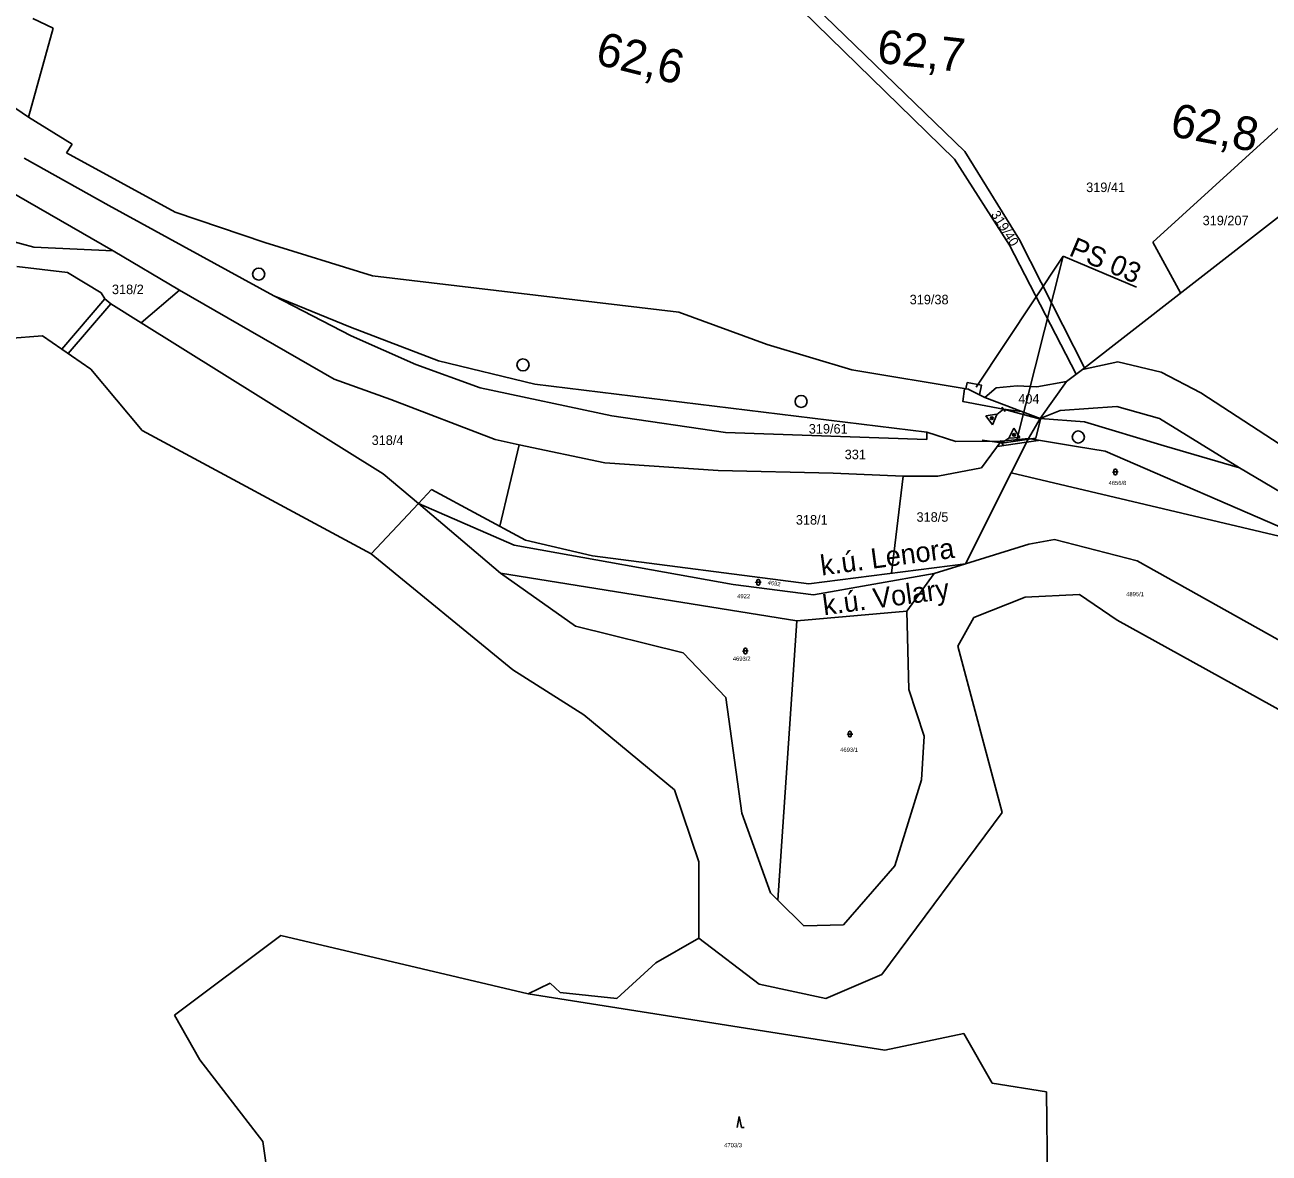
# Model space of a CAD drawing. Extents: x -805826 to -803822, y -1165880 to -1164382.
# Drawn here: x -805114.2 to -804669.5, y -1165376.6 to -1164973.4 of the extents above; entities that cross this region are included whole.
import ezdxf

# ---------------------------------------------------------------- set-up
doc = ezdxf.new("R2010")
doc.units = 0
for name, color, linetype in [('Default', 7, 'Continuous'), ('kilometráž - 2880', 7, 'Continuous'), ('kn_celek - Cisla pozemkovych parcel', 7, 'Continuous'), ('kn_celek - Hranice KU 1_2880', 7, 'Continuous'), ('kn_celek - Hranice parcel', 7, 'Continuous'), ('kn_celek - názvy ku 1_2880', 7, 'Continuous'), ('kn_celek - Vnitrni kresby', 7, 'Continuous'), ('kn_celek - Znacky kultur', 7, 'Continuous'), ('plochy - DZ_ostat', 7, 'Continuous'), ('plochy - SZDC', 7, 'Continuous'), ('plochy - TZ_zpf', 7, 'Continuous'), ('PSR_C2_3_celsit_Lenora - PS03', 7, 'Continuous'), ('SOPS', 7, 'Continuous')]:
    doc.layers.add(name, color=color, linetype=linetype)

# ---------------------------------------------------------------- blocks, each defined once
blk = doc.blocks.new('316')
at = {"layer": 'Default'}
for p, q in [((-8.3, 10), (-10, 8.1)), ((-5, 10), (-8.3, 10)), ((-5, 15.5), (-5, 4.5)), ((-5, 10), (5, 10)), ((0.5, 20), (-0.5, 20)), ((-0.5, 0), (0.5, 0)), ((5, 4.5), (5, 15.5)), ((10, 10), (5, 10))]:
    blk.add_line(p, q, dxfattribs=at)
for centre, start, end in [((-0.5, 15.5), 90, 180), ((-0.5, 4.5), 180, 270), ((0.5, 15.5), 0, 90), ((0.5, 4.5), 270, 0)]:
    blk.add_arc(centre, 4.5, start, end, dxfattribs=at)
blk = doc.blocks.new('308')
at = {"layer": 'Default'}
for p, q in [((-7.5, 0.2), (0, 40.2)), ((0, 40.2), (7.5, 0.2)), ((7.5, 0.2), (17.5, 0.2))]:
    blk.add_line(p, q, dxfattribs=at)

msp = doc.modelspace()

# ---------------------------------------------------------------- linework, layer by layer
at = {"layer": 'kilometráž - 2880'}
for centre in [(-805030.64, -1165062.45), (-804936.17, -1165094.91), (-804836.78, -1165107.96), (-804737.69, -1165120.69)]:
    msp.add_circle(centre, 2.16, dxfattribs=at)
at = {"layer": 'kn_celek - Hranice KU 1_2880'}
for p, q in [((-804701.79, -1165069.72), (-804618.36, -1165004.7)), ((-804736.13, -1165096.49), (-804701.79, -1165069.72)), ((-805120.21, -1165085.52), (-805107.91, -1165084.54)), ((-805107.91, -1165084.54), (-805090.67, -1165096.41)), ((-805090.67, -1165096.41), (-805072.24, -1165118.38)), ((-804741.92, -1165100.8), (-804736.13, -1165096.49)), ((-804751.26, -1165114.04), (-804741.92, -1165100.8)), ((-805072.24, -1165118.38), (-804990.43, -1165162.44)), ((-804761.65, -1165133.49), (-804755.48, -1165121.19)), ((-804777.95, -1165165.95), (-804761.65, -1165133.49)), ((-804973.55, -1165144.43), (-804968.85, -1165139.42)), ((-804968.85, -1165139.42), (-804935.25, -1165157.52)), ((-804990.43, -1165162.44), (-804973.55, -1165144.43)), ((-804935.25, -1165157.52), (-804911.29, -1165163.1)), ((-804911.29, -1165163.1), (-804834.02, -1165173.21)), ((-804834.02, -1165173.21), (-804777.95, -1165165.95))]:
    msp.add_line(p, q, dxfattribs=at)
at = {"layer": 'kn_celek - Hranice parcel'}
for p, q in [((-804837.56, -1164961.21), (-804778.25, -1165018.66)), ((-804781.99, -1165021.41), (-804842.42, -1164962.28)), ((-805112.96, -1165006.31), (-805104.08, -1164974.52)), ((-805104.08, -1164974.52), (-805111.37, -1164971.04)), ((-804711.07, -1165051.06), (-804629.65, -1164976.8)), ((-805139.43, -1164988.32), (-805112.96, -1165006.31)), ((-805174.61, -1165001.14), (-805082.67, -1165054.14)), ((-804701.79, -1165069.72), (-804618.36, -1165004.7)), ((-805097.29, -1165016.07), (-805112.96, -1165006.31)), ((-805099.28, -1165019.07), (-805097.29, -1165016.07)), ((-805060.5, -1165040.27), (-805099.28, -1165019.07)), ((-804778.25, -1165018.66), (-804758.75, -1165050.15)), ((-805084.18, -1165037.92), (-805114.48, -1165020.99)), ((-804762.33, -1165052.09), (-804781.99, -1165021.41)), ((-805111.01, -1165052.83), (-805172.69, -1165036.29)), ((-805025.27, -1165070.2), (-805084.18, -1165037.92)), ((-805028.48, -1165051.18), (-805060.5, -1165040.27)), ((-804758.75, -1165050.15), (-804735.46, -1165095.96)), ((-805111.01, -1165052.83), (-805082.67, -1165054.14)), ((-805082.67, -1165054.14), (-805058.92, -1165068.18)), ((-804989.96, -1165063.05), (-805028.48, -1165051.18)), ((-804762.33, -1165052.09), (-804738.45, -1165098.21)), ((-804701.13, -1165069.2), (-804711.07, -1165051.06)), ((-805098.97, -1165061.86), (-805117.06, -1165059.74)), ((-805086.95, -1165069.13), (-805098.97, -1165061.86)), ((-804880.41, -1165076.04), (-804989.96, -1165063.05)), ((-805085.68, -1165071.33), (-805086.95, -1165069.13)), ((-805083.5, -1165073.08), (-805085.68, -1165071.33)), ((-805058.92, -1165068.18), (-805072.6, -1165079.88)), ((-805058.92, -1165068.18), (-805003.62, -1165099.97)), ((-804997.78, -1165081.45), (-805025.27, -1165070.2)), ((-804997.61, -1165084.5), (-805025.27, -1165070.2)), ((-804736.13, -1165096.49), (-804701.79, -1165069.72)), ((-805072.6, -1165079.88), (-805083.5, -1165073.08)), ((-804848.93, -1165087.58), (-804880.41, -1165076.04)), ((-804986.13, -1165133.88), (-805072.6, -1165079.88)), ((-805120.21, -1165085.52), (-805107.91, -1165084.54)), ((-805107.91, -1165084.54), (-805090.67, -1165096.41)), ((-804966.37, -1165093.45), (-804997.78, -1165081.45)), ((-804974.47, -1165094.78), (-804997.61, -1165084.5)), ((-804818.68, -1165096.66), (-804848.93, -1165087.58)), ((-804931.9, -1165101.79), (-804966.37, -1165093.45)), ((-804736.13, -1165096.49), (-804723.61, -1165093.79)), ((-804723.61, -1165093.79), (-804708.12, -1165097.52)), ((-805090.67, -1165096.41), (-805072.24, -1165118.38)), ((-804951.5, -1165103.08), (-804974.47, -1165094.78)), ((-804777.08, -1165103.56), (-804818.68, -1165096.66)), ((-804741.92, -1165100.8), (-804736.13, -1165096.49)), ((-804708.12, -1165097.52), (-804693.95, -1165104.94)), ((-805003.62, -1165099.97), (-804983.39, -1165107.24)), ((-804904.36, -1165113.06), (-804951.5, -1165103.08)), ((-804791.88, -1165118.97), (-804931.9, -1165101.79)), ((-804771.09, -1165106.6), (-804777.08, -1165103.56)), ((-804767.08, -1165103.1), (-804771.09, -1165106.6)), ((-804759.5, -1165102.35), (-804767.08, -1165103.1)), ((-804752.56, -1165102.78), (-804759.5, -1165102.35)), ((-804741.92, -1165100.8), (-804752.56, -1165102.78)), ((-804751.26, -1165114.04), (-804741.92, -1165100.8)), ((-804983.39, -1165107.24), (-804946.17, -1165121.59)), ((-804771.09, -1165106.6), (-804751.26, -1165114.04)), ((-804693.95, -1165104.94), (-804660.4, -1165126.64)), ((-804863.76, -1165119.07), (-804904.36, -1165113.06)), ((-804755.48, -1165121.19), (-804751.26, -1165114.04)), ((-805072.24, -1165118.38), (-804990.43, -1165162.44)), ((-804863.76, -1165119.07), (-804791.87, -1165121.58)), ((-804781.51, -1165122.32), (-804791.88, -1165118.97)), ((-804791.87, -1165121.58), (-804791.88, -1165118.97)), ((-804765.27, -1165122.22), (-804755.48, -1165121.19)), ((-804761.65, -1165133.49), (-804755.48, -1165121.19)), ((-804946.17, -1165121.59), (-804937.48, -1165123.52)), ((-804937.48, -1165123.52), (-804944.46, -1165152.56)), ((-804937.48, -1165123.52), (-804906.97, -1165129.95)), ((-804781.51, -1165122.32), (-804765.27, -1165122.22)), ((-804772.23, -1165131.74), (-804765.27, -1165122.22)), ((-804906.97, -1165129.95), (-804866.41, -1165132.62)), ((-804986.13, -1165133.88), (-804973.55, -1165144.43)), ((-804866.41, -1165132.62), (-804825.3, -1165133.59)), ((-804825.3, -1165133.59), (-804800.3, -1165134.73)), ((-804800.3, -1165134.73), (-804804.4, -1165169.37)), ((-804800.3, -1165134.73), (-804787.89, -1165134.71)), ((-804787.89, -1165134.71), (-804772.23, -1165131.74)), ((-804777.95, -1165165.95), (-804761.65, -1165133.49)), ((-804761.65, -1165133.49), (-804651.28, -1165159.6)), ((-804973.55, -1165144.43), (-804968.85, -1165139.42)), ((-804968.85, -1165139.42), (-804935.25, -1165157.52)), ((-804990.43, -1165162.44), (-804973.55, -1165144.43)), ((-804973.55, -1165144.43), (-804944.25, -1165169.38)), ((-804973.55, -1165144.43), (-804939.37, -1165159.28)), ((-804939.37, -1165159.28), (-804861.09, -1165173.4)), ((-804935.25, -1165157.52), (-804911.29, -1165163.1)), ((-804777.95, -1165165.95), (-804755.4, -1165159)), ((-804755.4, -1165159), (-804746.18, -1165157.34)), ((-804746.18, -1165157.34), (-804716.61, -1165164.88)), ((-804990.43, -1165162.44), (-804939.85, -1165203.91)), ((-804911.29, -1165163.1), (-804834.02, -1165173.21)), ((-804716.61, -1165164.88), (-804650.46, -1165202.02)), ((-804944.25, -1165169.38), (-804917.4, -1165188.34)), ((-804944.25, -1165169.38), (-804838.24, -1165186.4)), ((-804834.02, -1165173.21), (-804777.95, -1165165.95)), ((-804832.28, -1165177.14), (-804789.19, -1165169.41)), ((-804798.93, -1165182.88), (-804789.19, -1165169.41)), ((-804789.19, -1165169.41), (-804777.95, -1165165.95)), ((-804861.09, -1165173.4), (-804832.28, -1165177.14)), ((-804775.05, -1165185.13), (-804756.66, -1165177.95)), ((-804756.66, -1165177.95), (-804737.23, -1165176.92)), ((-804737.23, -1165176.92), (-804723.84, -1165186.09)), ((-804838.24, -1165186.4), (-804798.93, -1165182.88)), ((-804798.22, -1165210.97), (-804798.93, -1165182.88)), ((-804838.24, -1165186.4), (-804845.1, -1165286.24)), ((-804780.72, -1165195.43), (-804775.05, -1165185.13)), ((-804723.84, -1165186.09), (-804641.91, -1165231.43)), ((-804917.4, -1165188.34), (-804878.89, -1165197.85)), ((-804764.95, -1165254.92), (-804780.72, -1165195.43)), ((-804878.89, -1165197.85), (-804863.7, -1165213.78)), ((-804939.85, -1165203.91), (-804914.38, -1165220.02)), ((-804863.7, -1165213.78), (-804857.91, -1165255.12)), ((-804792.79, -1165227.64), (-804798.22, -1165210.97)), ((-804914.38, -1165220.02), (-804882.07, -1165246.78)), ((-804793.75, -1165243.18), (-804792.79, -1165227.64)), ((-804803.28, -1165273.99), (-804793.75, -1165243.18)), ((-804882.07, -1165246.78), (-804873.29, -1165272.52)), ((-804857.91, -1165255.12), (-804847.72, -1165283.64)), ((-804807.87, -1165312.77), (-804764.95, -1165254.92)), ((-804873.29, -1165272.52), (-804873.29, -1165299.84)), ((-804821.57, -1165295.06), (-804803.28, -1165273.99)), ((-804847.72, -1165283.64), (-804845.1, -1165286.24)), ((-804845.1, -1165286.24), (-804835.83, -1165295.45)), ((-805022.67, -1165298.88), (-805060.78, -1165327.35)), ((-804934.36, -1165319.74), (-805022.67, -1165298.88)), ((-804835.83, -1165295.45), (-804821.57, -1165295.06)), ((-804873.29, -1165299.84), (-804888.66, -1165308.62)), ((-804873.29, -1165299.84), (-804851.7, -1165316.28)), ((-804888.66, -1165308.62), (-804902.65, -1165321.41)), ((-804926.5, -1165315.87), (-804934.36, -1165319.74)), ((-804922.9, -1165319.21), (-804926.5, -1165315.87)), ((-804851.7, -1165316.28), (-804827.96, -1165321.42)), ((-804827.96, -1165321.42), (-804807.87, -1165312.77)), ((-804934.36, -1165319.74), (-804806.87, -1165339.86)), ((-804902.65, -1165321.41), (-804922.9, -1165319.21)), ((-805060.78, -1165327.35), (-805051.65, -1165343.34)), ((-804806.87, -1165339.86), (-804778.61, -1165333.89)), ((-804778.61, -1165333.89), (-804768.44, -1165351.57)), ((-805051.65, -1165343.34), (-805029.16, -1165372.5)), ((-804768.44, -1165351.57), (-804749.1, -1165354.73)), ((-804749.1, -1165354.73), (-804748.68, -1165385.76)), ((-805029.16, -1165372.5), (-805023.85, -1165410.8))]:
    msp.add_line(p, q, dxfattribs=at)
at = {"layer": 'kn_celek - Vnitrni kresby'}
for p, q in [((-805085.68, -1165071.33), (-805101, -1165089.3)), ((-805083.5, -1165073.08), (-805098.74, -1165090.85)), ((-804751.26, -1165114.04), (-804744.11, -1165111.21)), ((-804744.11, -1165111.21), (-804723.96, -1165109.77)), ((-804723.96, -1165109.77), (-804708.7, -1165114.11)), ((-804708.7, -1165114.11), (-804680.02, -1165131.72))]:
    msp.add_line(p, q, dxfattribs=at)
at = {"layer": 'plochy - DZ_ostat'}
for p, q in [((-804755.48, -1165121.19), (-804765.27, -1165122.22)), ((-804755.48, -1165121.19), (-804756.18, -1165122.58)), ((-804756.18, -1165122.58), (-804755.48, -1165121.19)), ((-804751.97, -1165121.77), (-804755.48, -1165121.19)), ((-804765.27, -1165122.22), (-804766.67, -1165124.13)), ((-804766.67, -1165124.13), (-804756.18, -1165122.58))]:
    msp.add_line(p, q, dxfattribs=at)
for points in [[(-804751.97, -1165121.77), (-804752.01, -1165121.96), (-804756.18, -1165122.58)], [(-804756.18, -1165122.58), (-804752.01, -1165121.96), (-804751.97, -1165121.77)]]:
    msp.add_lwpolyline(points, dxfattribs=at)
at = {"layer": 'plochy - SZDC'}
for p, q in [((-805112.96, -1165006.31), (-805139.43, -1164988.32)), ((-805097.29, -1165016.07), (-805112.96, -1165006.31)), ((-805099.28, -1165019.07), (-805097.29, -1165016.07)), ((-805060.5, -1165040.27), (-805099.28, -1165019.07)), ((-805114.48, -1165020.99), (-805084.18, -1165037.92)), ((-805084.18, -1165037.92), (-805025.27, -1165070.2)), ((-805028.48, -1165051.18), (-805060.5, -1165040.27)), ((-804989.96, -1165063.05), (-805028.48, -1165051.18)), ((-804880.41, -1165076.04), (-804989.96, -1165063.05)), ((-805025.27, -1165070.2), (-804997.78, -1165081.45)), ((-804848.93, -1165087.58), (-804880.41, -1165076.04)), ((-804997.78, -1165081.45), (-804966.37, -1165093.45)), ((-804818.68, -1165096.66), (-804848.93, -1165087.58)), ((-804966.37, -1165093.45), (-804931.9, -1165101.79)), ((-804777.08, -1165103.56), (-804818.68, -1165096.66)), ((-804931.9, -1165101.79), (-804791.88, -1165118.97)), ((-804771.09, -1165106.6), (-804777.08, -1165103.56)), ((-804767.08, -1165103.1), (-804771.09, -1165106.6)), ((-804759.5, -1165102.35), (-804767.08, -1165103.1)), ((-804752.56, -1165102.78), (-804759.5, -1165102.35)), ((-804741.92, -1165100.8), (-804752.56, -1165102.78)), ((-804751.26, -1165114.04), (-804741.92, -1165100.8)), ((-804771.09, -1165106.6), (-804751.26, -1165114.04)), ((-804751.26, -1165114.04), (-804771.09, -1165106.6)), ((-804755.48, -1165121.19), (-804751.26, -1165114.04)), ((-804751.26, -1165114.04), (-804755.48, -1165121.19)), ((-804735.44, -1165115.31), (-804751.26, -1165114.04)), ((-804706.98, -1165123.89), (-804735.44, -1165115.31)), ((-804791.88, -1165118.97), (-804781.51, -1165122.32)), ((-804765.27, -1165122.22), (-804755.48, -1165121.19)), ((-804755.48, -1165121.19), (-804751.97, -1165121.77)), ((-804781.51, -1165122.32), (-804765.27, -1165122.22)), ((-804751.97, -1165121.77), (-804738.35, -1165124.03)), ((-804738.35, -1165124.03), (-804728.07, -1165125.68)), ((-804728.07, -1165125.68), (-804647.39, -1165160.7)), ((-804680.02, -1165131.72), (-804706.98, -1165123.89)), ((-804619.47, -1165167.61), (-804680.02, -1165131.72))]:
    msp.add_line(p, q, dxfattribs=at)
at = {"layer": 'plochy - TZ_zpf'}
for p, q in [((-804777.43, -1165101.18), (-804777.83, -1165103.43)), ((-804777.83, -1165103.43), (-804777.08, -1165103.56)), ((-804777.08, -1165103.56), (-804773.04, -1165105.61))]:
    msp.add_line(p, q, dxfattribs=at)
for points in [[(-804777.83, -1165103.43), (-804777.43, -1165101.18)], [(-804777.43, -1165101.18), (-804772.31, -1165102.11), (-804773.04, -1165105.61)], [(-804773.04, -1165105.61), (-804772.31, -1165102.11), (-804777.43, -1165101.18)]]:
    msp.add_lwpolyline(points, dxfattribs=at)
at = {"layer": 'PSR_C2_3_celsit_Lenora - PS03'}
for p, q in [((-804766.8, -1165112.61), (-804764.46, -1165110.75)), ((-804765.05, -1165109.97), (-804763.84, -1165111.51)), ((-804764.45, -1165110.74), (-804758, -1165111.59)), ((-804770.79, -1165113.13), (-804766.83, -1165112.57)), ((-804770.79, -1165113.13), (-804768.38, -1165116.31)), ((-804768.11, -1165113.84), (-804769.08, -1165113.75)), ((-804768.22, -1165114.22), (-804769.08, -1165114.11)), ((-804766.82, -1165112.61), (-804768.38, -1165116.31)), ((-804762.57, -1165121.08), (-804765.06, -1165122.76)), ((-804762.55, -1165121.09), (-804760.71, -1165117.52)), ((-804758.56, -1165120.89), (-804762.55, -1165121.13)), ((-804761.17, -1165119.97), (-804760.21, -1165120.13)), ((-804761.04, -1165119.6), (-804760.19, -1165119.77)), ((-804758.56, -1165120.89), (-804760.71, -1165117.52)), ((-804772.01, -1165121.85), (-804765.07, -1165122.76)), ((-804764.53, -1165123.58), (-804765.62, -1165121.95))]:
    msp.add_line(p, q, dxfattribs=at)
msp.add_lwpolyline([(-804776.85, -1165103.59), (-804778.34, -1165103.41), (-804778.92, -1165108.04), (-804764.44, -1165110.74), (-804751.18, -1165114.27), (-804752.83, -1165121.07), (-804765.02, -1165122.88)], dxfattribs=at)
for centre in [(-804768.63, -1165113.95), (-804760.65, -1165119.89)]:
    msp.add_circle(centre, 0.5, dxfattribs=at)
at = {"layer": 'SOPS'}
for p, q in [((-804774.16, -1165102.89), (-804743.04, -1165055.99)), ((-804743.04, -1165055.99), (-804759.77, -1165122.22)), ((-804743.04, -1165055.99), (-804716.89, -1165067.12))]:
    msp.add_line(p, q, dxfattribs=at)

# ---------------------------------------------------------------- block references
at = {"layer": 'kn_celek - Znacky kultur', "xscale": 0.1, "yscale": 0.10000000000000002}
for name, p in [('316', (-804724.45, -1165134.16)), ('316', (-804852.07, -1165173.61)), ('316', (-804856.68, -1165198.13)), ('316', (-804819.33, -1165227.87)), ('308', (-804858.87, -1165367.51))]:
    msp.add_blockref(name, p, dxfattribs=at)

# ---------------------------------------------------------------- texts
at = {"layer": 'kilometráž - 2880'}
for s, rotation, p in [('62,6', 346.0635, (-804910.76, -1164987.27)), ('62,7', 353.5516, (-804809.94, -1164986.84)), ('62,8', 349.2241, (-804705.27, -1165012.99))]:
    msp.add_text(s, height=12, rotation=rotation, dxfattribs=at).set_placement(p)
at = {"layer": 'kn_celek - Cisla pozemkovych parcel'}
for s, height, p in [('319/41', 3.4, (-804734.88, -1165033.13)), ('319/207', 3.4, (-804693.25, -1165044.98)), ('318/2', 3.4, (-805083.09, -1165069.61)), ('319/38', 3.4, (-804797.96, -1165073.25)), ('404', 3.4, (-804759.16, -1165108.74)), ('319/61', 3.4, (-804834.03, -1165119.45)), ('318/4', 3.4, (-804990.27, -1165123.52)), ('331', 3.4, (-804821.18, -1165128.61)), ('4656/8', 1.5, (-804726.86, -1165137.85)), ('318/5', 3.4, (-804795.51, -1165150.97)), ('318/1', 3.4, (-804838.64, -1165151.98)), ('4922', 1.5, (-804859.6, -1165178.29)), ('4895/1', 1.5, (-804720.57, -1165177.58)), ('4693/2', 1.5, (-804861.17, -1165200.67)), ('4693/1', 1.5, (-804822.79, -1165233.22)), ('4703/3', 1.5, (-804864.24, -1165374.53))]:
    msp.add_text(s, height=height, dxfattribs=at).set_placement(p)
for s, height, rotation, p in [('319/40', 3.4, 302.3103, (-804769.04, -1165041.12)), ('4692', 1.5, 352.1411, (-804848.79, -1165173.43))]:
    msp.add_text(s, height=height, rotation=rotation, dxfattribs=at).set_placement(p)
at = {"layer": 'kn_celek - názvy ku 1_2880'}
for s, p in [('k.ú. Lenora', (-804829.4, -1165170.21)), ('k.ú. Volary', (-804828.57, -1165184.42))]:
    msp.add_text(s, height=7.2, rotation=7.6309, dxfattribs=at).set_placement(p)
at = {"layer": 'SOPS'}
msp.add_text('PS 03', height=7.2, rotation=336.9516, dxfattribs=at).set_placement((-804741.39, -1165055.67))

doc.saveas('drawing.dxf')
